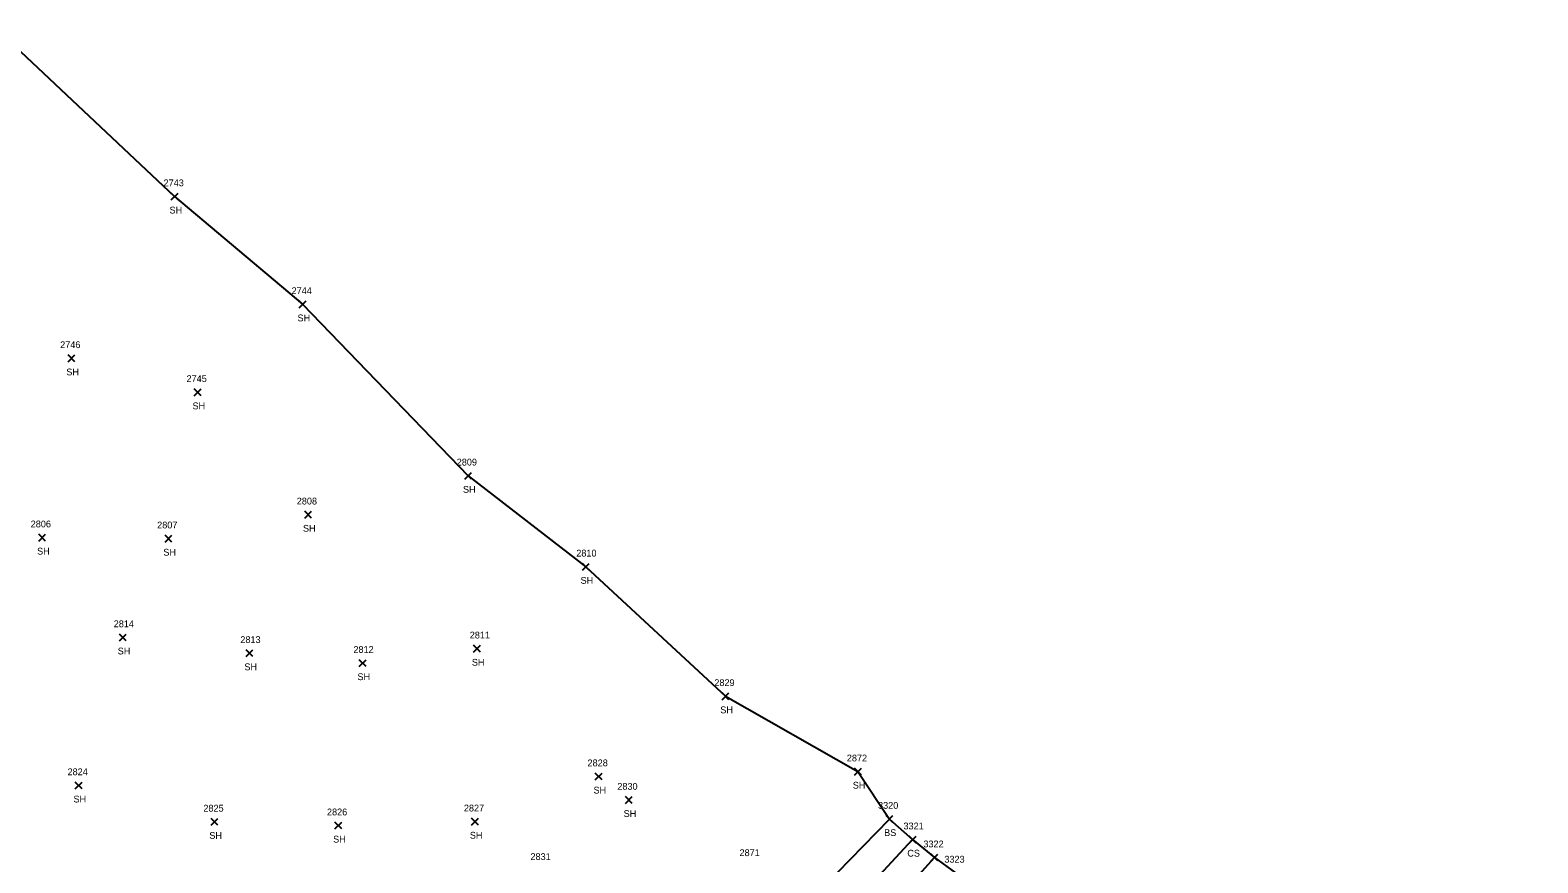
# Model space of a CAD drawing. Extents: x 1472233 to 1475777, y 540726 to 543442.
# Drawn here: x 1474263.9 to 1474707, y 542554.7 to 542799.3 of the extents above; entities that cross this region are included whole.
import ezdxf

# ---------------------------------------------------------------- set-up
doc = ezdxf.new("R2010")
doc.units = 0
for name, color, linetype in [('L_A', 7, 'Continuous'), ('L_I', 7, 'Continuous'), ('L_TIC', 7, 'Continuous'), ('LELB', 7, 'Continuous'), ('LSOGP', 7, 'Continuous'), ('P_I', 7, 'Continuous')]:
    doc.layers.add(name, color=color, linetype=linetype)

msp = doc.modelspace()

# ---------------------------------------------------------------- linework, layer by layer
at = {"layer": 'L_TIC'}
for points in [[(1474305.41, 542749.42), (1474307.41, 542751.42)], [(1474307.41, 542749.42), (1474305.41, 542751.42)], [(1474343.02, 542717.74), (1474345.02, 542719.74)], [(1474345.02, 542717.74), (1474343.02, 542719.74)], [(1474275.08, 542701.87), (1474277.08, 542703.87)], [(1474277.08, 542701.87), (1474275.08, 542703.87)], [(1474312.16, 542691.91), (1474314.16, 542693.91)], [(1474314.16, 542691.91), (1474312.16, 542693.91)], [(1474391.64, 542667.39), (1474393.64, 542669.39)], [(1474393.64, 542667.39), (1474391.64, 542669.39)], [(1474344.62, 542655.95), (1474346.62, 542657.95)], [(1474346.62, 542655.95), (1474344.62, 542657.95)], [(1474266.5, 542649.22), (1474268.5, 542651.22)], [(1474268.5, 542649.22), (1474266.5, 542651.22)], [(1474303.61, 542648.92), (1474305.61, 542650.92)], [(1474305.61, 542648.92), (1474303.61, 542650.92)], [(1474426.2, 542640.66), (1474428.2, 542642.66)], [(1474428.2, 542640.66), (1474426.2, 542642.66)], [(1474290.2, 542619.9), (1474292.2, 542621.9)], [(1474292.2, 542619.9), (1474290.2, 542621.9)], [(1474327.4, 542615.25), (1474329.4, 542617.25)], [(1474329.4, 542615.25), (1474327.4, 542617.25)], [(1474394.24, 542616.59), (1474396.24, 542618.59)], [(1474396.24, 542616.59), (1474394.24, 542618.59)], [(1474360.64, 542612.35), (1474362.64, 542614.35)], [(1474362.64, 542612.35), (1474360.64, 542614.35)], [(1474467.26, 542602.61), (1474469.26, 542604.61)], [(1474469.26, 542602.61), (1474467.26, 542604.61)], [(1474506.18, 542580.48), (1474508.18, 542582.48)], [(1474508.18, 542580.48), (1474506.18, 542582.48)], [(1474277.19, 542576.42), (1474279.19, 542578.42)], [(1474279.19, 542576.42), (1474277.19, 542578.42)], [(1474429.99, 542579.04), (1474431.99, 542581.04)], [(1474431.99, 542579.04), (1474429.99, 542581.04)], [(1474438.84, 542572.15), (1474440.84, 542574.15)], [(1474440.84, 542572.15), (1474438.84, 542574.15)], [(1474515.44, 542566.56), (1474517.44, 542568.56)], [(1474517.44, 542566.56), (1474515.44, 542568.56)], [(1474317.11, 542565.73), (1474319.11, 542567.73)], [(1474319.11, 542565.73), (1474317.11, 542567.73)], [(1474353.49, 542564.63), (1474355.49, 542566.63)], [(1474355.49, 542564.63), (1474353.49, 542566.63)], [(1474393.65, 542565.78), (1474395.65, 542567.78)], [(1474395.65, 542565.78), (1474393.65, 542567.78)], [(1474522.25, 542560.51), (1474524.25, 542562.51)], [(1474524.25, 542560.51), (1474522.25, 542562.51)], [(1474528.67, 542555.23), (1474530.67, 542557.23)], [(1474530.67, 542555.23), (1474528.67, 542557.23)]]:
    msp.add_lwpolyline(points, dxfattribs=at)
at = {"layer": 'LELB'}
for points in [[(1474160.18, 542201.33), (1474168.88, 542204.85), (1474199.76, 542233.59), (1474232.18, 542271.17), (1474267.12, 542308.88), (1474299.34, 542340.87), (1474332.23, 542375.84), (1474366.86, 542412.72), (1474402.09, 542448.8), (1474432.87, 542480.81), (1474470.66, 542520.55), (1474516.44, 542567.56)], [(1473906.31, 542415.11), (1473928.48, 542392.67), (1473965.32, 542353.55), (1473983.11, 542341.15), (1474025.37, 542302.76), (1474058.47, 542271.21), (1474097.38, 542229.91), (1474138.31, 542198.57), (1474151.22, 542193.05), (1474160.36, 542193.58), (1474173.74, 542199.32), (1474204.33, 542229.44), (1474238.35, 542265.7), (1474274.3, 542301.58), (1474305.47, 542334.43), (1474340.21, 542369.37), (1474374.08, 542405.17), (1474409.17, 542441.59), (1474439.3, 542474.71), (1474478.4, 542513.06), (1474523.25, 542561.51)], [(1474243.66, 542261.29), (1474279.95, 542296.56), (1474311.01, 542327.87), (1474346, 542363.32), (1474378.44, 542399.42), (1474414.78, 542435.18), (1474446.25, 542467.39), (1474485.02, 542506.72), (1474529.67, 542556.23)]]:
    msp.add_lwpolyline(points, dxfattribs=at)
at = {"layer": 'LSOGP'}
msp.add_lwpolyline([(1474254.32, 542799.27), (1474306.41, 542750.42), (1474344.02, 542718.74), (1474392.64, 542668.39), (1474427.2, 542641.66), (1474468.26, 542603.61), (1474507.18, 542581.48), (1474516.44, 542567.56), (1474523.25, 542561.51), (1474529.67, 542556.23), (1474535.84, 542551.74), (1474543.83, 542542.7), (1474552.8, 542535.14), (1474557.58, 542529.71), (1474565.22, 542523.07), (1474573.15, 542509.94), (1474599.19, 542484.98), (1474624.47, 542456.71), (1474647.57, 542430.49), (1474668.28, 542403.09), (1474672, 542403), (1474695.38, 542379.16), (1474702.24, 542370.13), (1474727.33, 542341.59)], dxfattribs=at)

# ---------------------------------------------------------------- texts
at = {"layer": 'L_A'}
for s, p in [('SH', (1474304.9, 542745.42)), ('SH', (1474342.51, 542713.74)), ('SH', (1474274.57, 542697.87)), ('SH', (1474311.65, 542687.91)), ('SH', (1474391.13, 542663.39)), ('SH', (1474344.11, 542651.95)), ('SH', (1474265.99, 542645.22)), ('SH', (1474303.09, 542644.92)), ('SH', (1474425.68, 542636.66)), ('SH', (1474289.68, 542615.9)), ('SH', (1474326.89, 542611.25)), ('SH', (1474393.73, 542612.59)), ('SH', (1474360.12, 542608.35)), ('SH', (1474466.74, 542598.61)), ('SH', (1474429.48, 542575.04)), ('SH', (1474505.66, 542576.48)), ('SH', (1474276.68, 542572.42)), ('SH', (1474438.33, 542568.15)), ('SH', (1474316.59, 542561.73)), ('SH', (1474393.14, 542561.78)), ('BS', (1474514.88, 542562.56)), ('SH', (1474352.98, 542560.63)), ('CS', (1474521.69, 542556.51))]:
    msp.add_text(s, height=2, dxfattribs=at).set_placement(p)
at = {"layer": 'L_I'}
for s, p in [('2743', (1474303.15, 542753.42)), ('2744', (1474340.76, 542721.74)), ('2746', (1474272.77, 542705.87)), ('2745', (1474309.9, 542695.91)), ('2809', (1474389.29, 542671.39)), ('2808', (1474342.29, 542659.95)), ('2806', (1474264.11, 542653.22)), ('2807', (1474301.27, 542652.92)), ('2810', (1474424.42, 542644.66)), ('2814', (1474288.5, 542623.9)), ('2813', (1474325.71, 542619.25)), ('2811', (1474393.12, 542620.59)), ('2812', (1474358.94, 542616.35)), ('2829', (1474464.99, 542606.61)), ('2872', (1474503.92, 542584.48)), ('2824', (1474274.93, 542580.42)), ('2828', (1474427.73, 542583.04)), ('2830', (1474436.49, 542576.15)), ('3320', (1474513.09, 542570.56)), ('2825', (1474314.85, 542569.73)), ('2826', (1474351.17, 542568.63)), ('2827', (1474391.39, 542569.78)), ('3321', (1474520.56, 542564.51)), ('3322', (1474526.41, 542559.23)), ('2831', (1474410.96, 542555.51)), ('2871', (1474472.38, 542556.66))]:
    msp.add_text(s, height=2, dxfattribs=at).set_placement(p)
at = {"layer": 'P_I'}
msp.add_text('3323', height=2, dxfattribs=at).set_placement((1474532.58, 542554.74))

doc.saveas('drawing.dxf')
